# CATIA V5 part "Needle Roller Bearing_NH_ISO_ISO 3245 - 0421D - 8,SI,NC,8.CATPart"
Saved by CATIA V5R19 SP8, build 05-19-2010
Part number: Needle Roller Bearing_NH_ISO_ISO 3245 - 0421D - 8,SI,NC,8
Revision: ANY
Definition: UNKNOWN
Nomenclature: Needle Roller Bearing_NH_ISO_ISO 3245 - 0421D - 8,SI,NC,8
Source: Unknown
Bounding box of the stored display mesh (mm): x -4 to 4, y -4 to 1.455, z -3.996 to 3.726
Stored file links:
  D:\Documents\1_Travail\2- 2I2D\1 - Cours et TD\2- TD\3-TD Assemblage\Pompe AirMan\Needle Roller Bearing_NH_ISO_ISO 3245 - 0421D - 8,SI,NC,8.CATPart
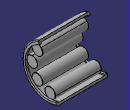
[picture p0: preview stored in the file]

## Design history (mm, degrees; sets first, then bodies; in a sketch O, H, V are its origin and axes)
Body1 "RollersDetailed" (main body)
  Solid1: solid without history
